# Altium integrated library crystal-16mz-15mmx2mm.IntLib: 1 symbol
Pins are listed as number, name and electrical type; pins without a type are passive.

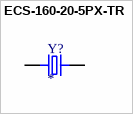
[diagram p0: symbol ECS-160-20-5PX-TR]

## ECS-160-20-5PX-TR
designator Y?
16 MHz Â±30ppm Crystal 20pF 40 Ohms HC-49/US; MF: ECS Inc.; MP: ECS-160-20-5PX-TR
footprint XTAL_ECS-160-20-5PX-TR
pins: 1, 2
